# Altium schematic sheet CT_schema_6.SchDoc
size 374 x 245 mm
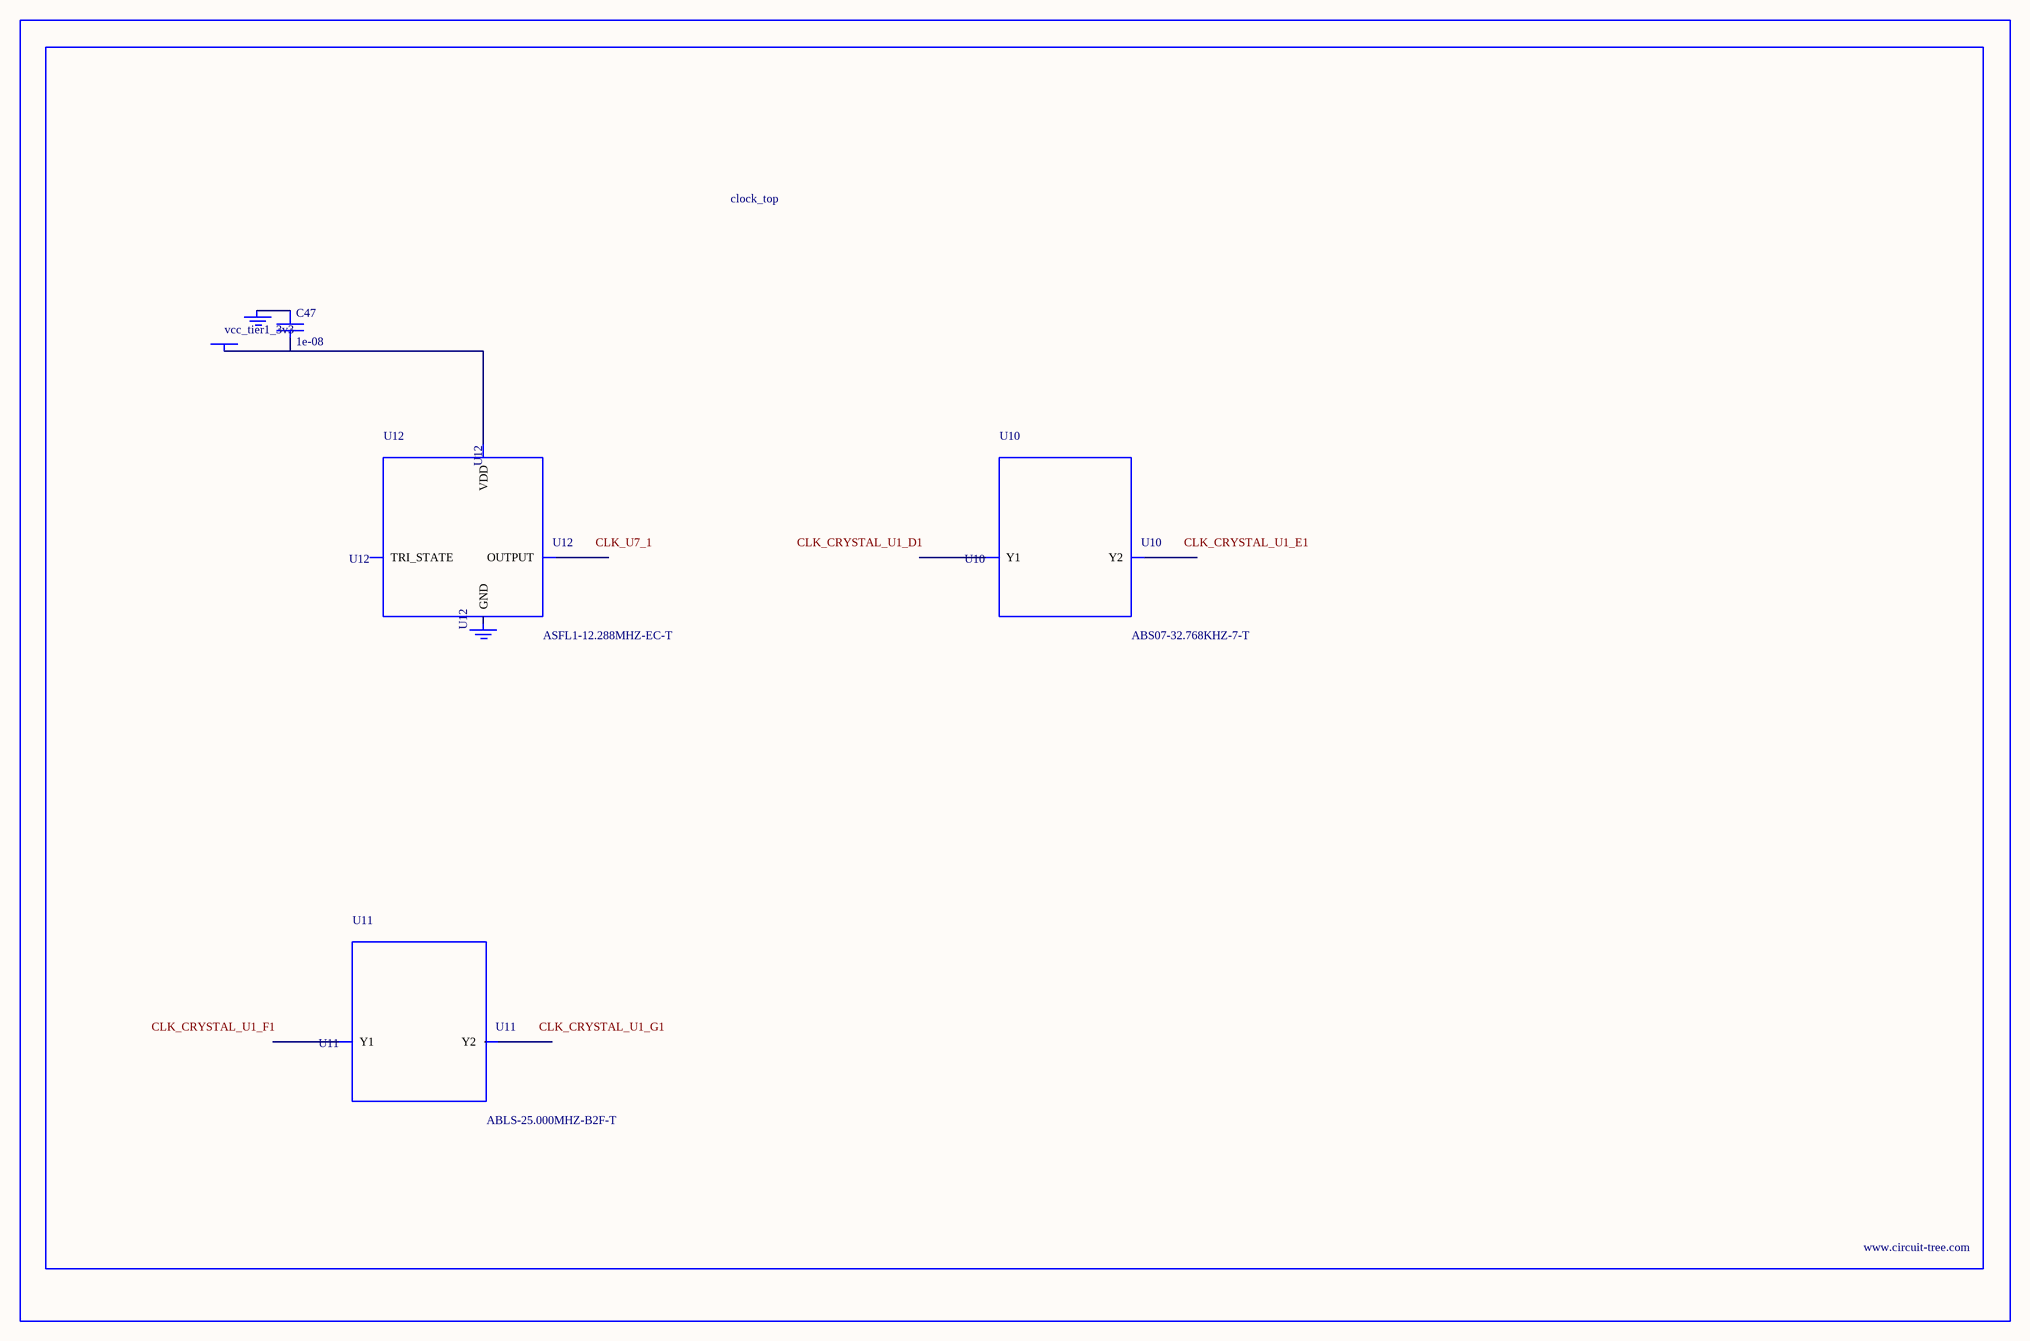
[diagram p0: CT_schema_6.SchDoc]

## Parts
BORDER5  (no value)
C47  1e-08  [C0402]
GND_INSTANCE_5_0  (no value)
GND_INSTANCE_5_1  (no value)
POWER_INSTANCE_5_0  vcc_tier1_3v3
U10  ABS07-32.768KHZ-7-T  [ABS07-32.768KHZ-7-T]
U11  ABLS-25.000MHZ-B2F-T  [ABLS-25.000MHZ-B2F-T]
U12  ASFL1-12.288MHZ-EC-T  [ASFL1]

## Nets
NetC47_1: C47.1 GND_INSTANCE_5_0.0(GND)
NetC47_2: C47.2 POWER_INSTANCE_5_0.0(PWR) U12.4(VDD)

Not connected (* = marked no-connect by the designer): GND_INSTANCE_5_1 0(GND); U10 1(Y1) 2(Y2); U11 1(Y1) 2(Y2); U12 1(TRI_STATE) 2(GND) 3(OUTPUT)

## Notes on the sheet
- Labels drawn without touching a wire or pin: CLK_CRYSTAL_U1_D1, CLK_CRYSTAL_U1_E1, CLK_CRYSTAL_U1_F1, CLK_CRYSTAL_U1_G1, CLK_U7_1

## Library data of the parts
BORDER5 = BORDER_PAGE5
C47 = C0402C103K3RAC
GND_INSTANCE_5_0 GND_INSTANCE_5_1 = GND
POWER_INSTANCE_5_0 = PWR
